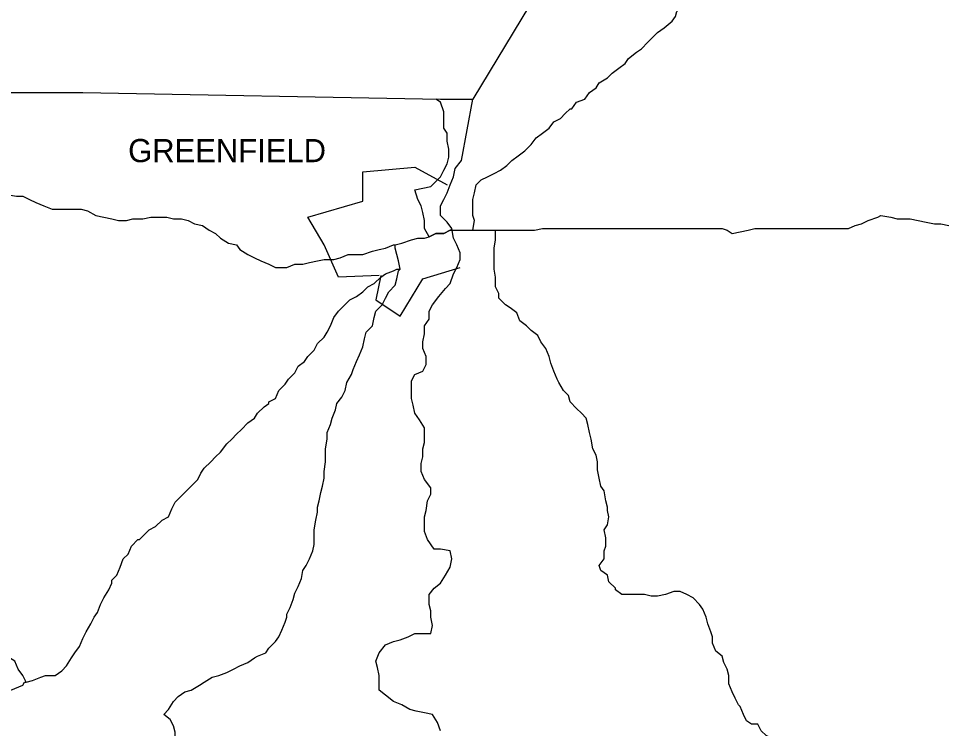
# Model space of a CAD drawing. Extents: x 0 to 40.2, y 0 to 22.
# Drawn here: x 4.34 to 5.119, y 18.795 to 19.393 of the extents above; entities that cross this region are included whole.
import ezdxf

# ---------------------------------------------------------------- set-up
doc = ezdxf.new("R2010")
doc.units = 0
doc.layers.add('Default', color=7, linetype='Continuous')

msp = doc.modelspace()

# ---------------------------------------------------------------- linework, layer by layer
at = {"layer": 'Default'}
for points in [[(5.09948, 19.94935), (5.06676, 19.89345), (4.97541, 19.74211), (4.72318, 19.3249)], [(4.80634, 19.31672), (4.81043, 19.32217), (4.81725, 19.3249), (4.82134, 19.33035), (4.8268, 19.33444), (4.82952, 19.33853), (4.83634, 19.34262), (4.84043, 19.34671), (4.84588, 19.3508), (4.85134, 19.35489), (4.85406, 19.35898), (4.86088, 19.36444), (4.86497, 19.36716), (4.87042, 19.37262), (4.87588, 19.37807), (4.87861, 19.3808), (4.88406, 19.38489), (4.89088, 19.39034), (4.8936, 19.39443), (4.89497, 19.39852), (4.89633, 19.39989)], [(3.95693, 19.3399), (4.11782, 19.33581), (4.31142, 19.33035), (4.39459, 19.33035), (4.69591, 19.3249), (4.72318, 19.3249)], [(4.69591, 18.79316), (4.69318, 18.79998), (4.68909, 18.8068), (4.68227, 18.80816), (4.67546, 18.80953), (4.67, 18.81089), (4.66318, 18.81498), (4.65637, 18.81771), (4.64955, 18.82316), (4.6441, 18.82725), (4.6441, 18.83407), (4.6441, 18.83952), (4.64273, 18.84634), (4.64137, 18.85179), (4.6441, 18.85861), (4.64955, 18.86543), (4.65637, 18.86815), (4.66182, 18.86952), (4.66864, 18.87224), (4.67409, 18.87497), (4.68091, 18.87497), (4.68773, 18.87497), (4.68909, 18.88179), (4.68773, 18.8886), (4.68773, 18.89406), (4.68636, 18.89951), (4.68636, 18.90769), (4.69045, 18.91315), (4.69591, 18.91724), (4.7, 18.92405), (4.70409, 18.93087), (4.70545, 18.93769), (4.70409, 18.9445), (4.69591, 18.94587), (4.69045, 18.94587), (4.685, 18.95405), (4.68227, 18.96087), (4.68227, 18.96632), (4.68227, 18.97314), (4.68364, 18.97859), (4.685, 18.98677), (4.68773, 18.99222), (4.68773, 18.99768), (4.68227, 19.00449), (4.67955, 19.01131), (4.67955, 19.01813), (4.68091, 19.02358), (4.68091, 19.0304), (4.68227, 19.03585), (4.68227, 19.04267), (4.68227, 19.04812), (4.67818, 19.05494), (4.67409, 19.0604), (4.67273, 19.06721), (4.67137, 19.07267), (4.67137, 19.07948), (4.67137, 19.08766), (4.67409, 19.09312), (4.68091, 19.09584), (4.68364, 19.1013), (4.68364, 19.10811), (4.68091, 19.11493), (4.68091, 19.12039), (4.68227, 19.1272), (4.68227, 19.13402), (4.68636, 19.13947), (4.68636, 19.14629), (4.68909, 19.15174), (4.69454, 19.15856), (4.7, 19.16538), (4.70409, 19.16947), (4.70681, 19.17765), (4.70954, 19.1831), (4.71227, 19.18992), (4.71227, 19.19537), (4.70954, 19.20219), (4.70681, 19.20764), (4.70545, 19.21583), (4.70136, 19.22128), (4.69591, 19.22673), (4.69591, 19.23491), (4.69863, 19.24037), (4.70136, 19.24582), (4.70409, 19.25264), (4.70681, 19.25945), (4.70818, 19.26627), (4.71363, 19.27309), (4.72318, 19.3249)], [(4.68636, 19.20901), (4.68227, 19.21583), (4.68227, 19.22264), (4.68091, 19.22946), (4.67955, 19.23491), (4.67682, 19.24037), (4.67409, 19.24855), (4.68091, 19.24991), (4.68773, 19.25127), (4.69182, 19.25536), (4.69591, 19.25945), (4.69863, 19.26491), (4.70136, 19.27036), (4.70272, 19.27582), (4.70272, 19.28263), (4.70136, 19.28945), (4.70136, 19.29627), (4.69863, 19.30036), (4.69863, 19.30854), (4.69863, 19.31399), (4.69591, 19.32217), (4.69182, 19.3249)], [(4.77226, 19.28672), (4.77635, 19.29218), (4.7818, 19.29627), (4.78726, 19.30036), (4.79135, 19.30581), (4.7968, 19.30854), (4.80089, 19.31263), (4.80498, 19.31672), (4.80634, 19.31672)], [(4.72318, 19.21446), (4.72454, 19.22264), (4.72318, 19.22673), (4.72318, 19.23491), (4.72318, 19.24037), (4.72454, 19.24582), (4.7259, 19.25264), (4.72999, 19.25673), (4.73545, 19.25945), (4.7409, 19.26218), (4.74635, 19.26491), (4.75181, 19.269), (4.7559, 19.27309), (4.76135, 19.27718), (4.7668, 19.28127), (4.77226, 19.28672), (4.77226, 19.28672)], [(4.6441, 19.17629), (4.61001, 19.17492), (4.59774, 19.20219), (4.58411, 19.22537), (4.63046, 19.239), (4.63046, 19.26354), (4.67409, 19.26764), (4.70136, 19.25264)], [(4.3196, 19.24446), (4.32506, 19.24446), (4.33051, 19.24446), (4.33869, 19.24309), (4.34414, 19.24309), (4.3496, 19.24037), (4.35505, 19.23764), (4.36187, 19.23491), (4.36869, 19.23219), (4.37414, 19.23219), (4.37959, 19.23219), (4.38641, 19.23219), (4.39323, 19.23219), (4.39868, 19.23082), (4.4055, 19.22673), (4.41232, 19.22537), (4.41913, 19.22401), (4.42459, 19.22264), (4.4314, 19.22264), (4.43686, 19.22401), (4.43822, 19.22401)], [(4.43822, 19.22401), (4.44504, 19.22401), (4.45185, 19.22537), (4.45867, 19.22537), (4.46549, 19.22537), (4.47094, 19.22401), (4.47776, 19.22401), (4.48321, 19.22264), (4.48867, 19.21992), (4.49548, 19.21855), (4.50094, 19.21446), (4.50639, 19.21173), (4.51048, 19.20764), (4.5173, 19.20355), (4.52412, 19.20219), (4.52684, 19.1981), (4.53366, 19.19401), (4.53911, 19.19128), (4.54457, 19.18856), (4.55138, 19.18583), (4.55684, 19.1831), (4.55956, 19.1831), (4.55956, 19.1831)], [(4.74226, 19.21446), (4.74772, 19.21446), (4.7559, 19.21446), (4.76271, 19.21446), (4.76953, 19.21446), (4.77499, 19.21446), (4.7818, 19.21583), (4.78726, 19.21583), (4.79407, 19.21583), (4.80089, 19.21583), (4.80771, 19.21583), (4.81452, 19.21583), (4.82134, 19.21583), (4.8268, 19.21583), (4.83498, 19.21583), (4.84043, 19.21583), (4.84588, 19.21583), (4.8527, 19.21583), (4.85952, 19.21583), (4.86633, 19.21583), (4.87315, 19.21583), (4.87861, 19.21583), (4.88542, 19.21583), (4.89224, 19.21583), (4.89906, 19.21583), (4.90587, 19.21583), (4.91133, 19.21583), (4.91951, 19.21583), (4.92496, 19.21583), (4.93314, 19.21583), (4.93723, 19.21446), (4.94132, 19.21173), (4.94814, 19.2131), (4.95496, 19.21446), (4.96041, 19.21583), (4.96723, 19.21583), (4.97404, 19.21583), (4.98086, 19.21583), (4.98768, 19.21583), (4.99313, 19.21583), (4.99995, 19.21583), (5.00677, 19.21583), (5.01222, 19.21583), (5.0204, 19.21583), (5.02585, 19.21583), (5.03267, 19.21583), (5.03949, 19.21583), (5.04494, 19.21855), (5.0504, 19.21992), (5.05585, 19.22264), (5.06403, 19.22537), (5.06676, 19.22673), (5.07494, 19.22537), (5.08039, 19.22401), (5.08857, 19.22401), (5.0913, 19.22401), (5.0913, 19.22401)], [(5.0913, 19.22401), (5.09812, 19.22264), (5.10493, 19.22128), (5.11175, 19.21992), (5.1172, 19.21992), (5.12402, 19.21855)], [(4.70545, 19.21446), (4.70409, 19.21446), (4.69863, 19.21173), (4.69182, 19.21173), (4.68636, 19.20901)], [(4.68636, 19.20901), (4.69182, 19.21173), (4.69863, 19.21173), (4.70409, 19.21446), (4.70545, 19.21446)], [(4.68636, 19.20901), (4.69182, 19.21173), (4.69863, 19.21173), (4.70409, 19.21446), (4.70545, 19.21446)], [(4.70545, 19.21446), (4.71227, 19.21446), (4.71772, 19.21446), (4.72318, 19.21446), (4.72318, 19.21446)], [(4.72318, 19.21446), (4.72999, 19.21446), (4.73681, 19.21446), (4.74226, 19.21446), (4.74226, 19.21446)], [(4.79407, 19.08903), (4.79135, 19.09584), (4.78862, 19.10266), (4.78726, 19.10811), (4.78453, 19.11493), (4.78044, 19.12039), (4.77771, 19.12584), (4.77226, 19.12993), (4.76817, 19.13402), (4.76271, 19.13811), (4.75999, 19.14493), (4.75453, 19.14902), (4.75044, 19.15174), (4.74499, 19.1572), (4.74499, 19.16129), (4.74226, 19.16674), (4.74226, 19.17492), (4.7409, 19.18174), (4.7409, 19.18719), (4.7409, 19.19401), (4.7409, 19.19946), (4.74226, 19.20628), (4.74226, 19.21173), (4.74226, 19.21446)], [(4.65773, 19.20219), (4.66318, 19.20355), (4.67137, 19.20628), (4.67682, 19.20764), (4.68227, 19.20764), (4.68636, 19.20901)], [(4.65773, 19.20219), (4.66318, 19.20355), (4.67137, 19.20628), (4.67682, 19.20764), (4.68227, 19.20764), (4.68636, 19.20901)], [(4.55956, 19.1831), (4.56638, 19.1831), (4.5732, 19.18583), (4.58002, 19.18583), (4.58547, 19.18719), (4.59229, 19.18856), (4.59774, 19.18992), (4.60592, 19.18992), (4.61137, 19.19128), (4.61819, 19.19401), (4.62501, 19.19401), (4.63046, 19.19401), (4.63864, 19.19674), (4.6441, 19.1981), (4.64955, 19.19946), (4.65637, 19.20219), (4.65773, 19.20219)], [(4.66182, 19.18174), (4.66046, 19.18856), (4.65909, 19.19401), (4.65773, 19.19946), (4.65773, 19.20219)], [(4.55138, 19.06994), (4.55684, 19.07267), (4.55956, 19.07948), (4.56502, 19.08494), (4.56775, 19.08903), (4.5732, 19.09448), (4.57593, 19.09993), (4.58138, 19.10402), (4.58411, 19.10811), (4.58956, 19.11357), (4.59229, 19.11902), (4.59774, 19.12448), (4.60047, 19.12857), (4.60319, 19.13402), (4.60592, 19.14084), (4.61001, 19.14629), (4.6141, 19.15038), (4.61956, 19.15583), (4.62501, 19.15856), (4.63046, 19.16265), (4.63455, 19.16674), (4.64001, 19.16947), (4.64546, 19.17492), (4.64955, 19.17765), (4.65637, 19.18038), (4.65909, 19.18174), (4.66182, 19.18174)], [(4.59229, 18.98132), (4.59365, 18.98677), (4.59501, 18.99359), (4.59638, 18.99904), (4.59774, 19.00586), (4.59774, 19.01131), (4.5991, 19.01949), (4.5991, 19.02358), (4.5991, 19.0304), (4.60047, 19.03858), (4.60047, 19.04403), (4.60319, 19.05085), (4.60456, 19.0563), (4.60728, 19.06312), (4.60865, 19.06858), (4.61274, 19.07403), (4.61547, 19.07948), (4.61683, 19.0863), (4.62092, 19.09312), (4.62228, 19.09721), (4.62501, 19.10402), (4.62774, 19.10948), (4.63046, 19.1163), (4.63183, 19.12311), (4.63319, 19.12857), (4.63864, 19.13402), (4.64001, 19.14084), (4.64137, 19.14629), (4.64682, 19.15174), (4.64955, 19.1572), (4.65228, 19.16265), (4.65773, 19.16811), (4.65909, 19.17356), (4.66046, 19.18038), (4.66182, 19.18174)], [(4.64546, 19.17629), (4.64137, 19.15583), (4.66182, 19.1422), (4.68091, 19.17356), (4.71227, 19.1831)], [(4.83634, 18.98132), (4.83498, 18.98677), (4.83361, 18.99495), (4.83089, 18.99904), (4.82952, 19.00586), (4.82816, 19.01268), (4.82816, 19.01949), (4.8268, 19.02495), (4.82407, 19.0304), (4.82271, 19.03858), (4.82134, 19.04403), (4.81998, 19.05085), (4.81861, 19.0563), (4.81452, 19.0604), (4.81043, 19.06449), (4.80498, 19.06994), (4.80362, 19.07539), (4.79953, 19.07948), (4.79544, 19.0863), (4.79407, 19.08903)], [(4.44231, 18.95405), (4.44504, 18.95678), (4.45049, 18.96223), (4.45595, 18.96496), (4.4614, 18.97041), (4.46685, 18.97314), (4.46958, 18.97995), (4.47231, 18.98541), (4.47776, 18.99086), (4.48185, 18.99495), (4.48594, 18.99904), (4.49139, 19.00449), (4.49412, 19.00995), (4.49685, 19.01404), (4.5023, 19.01949), (4.50639, 19.02358), (4.51048, 19.02767), (4.51594, 19.03449), (4.52003, 19.03858), (4.52412, 19.04267), (4.52821, 19.04676), (4.53366, 19.05221), (4.53911, 19.0563), (4.54184, 19.0604), (4.54729, 19.06585), (4.55138, 19.06858), (4.55138, 19.06994)], [(4.56638, 18.89133), (4.56911, 18.89678), (4.57184, 18.9036), (4.5732, 18.90906), (4.57593, 18.91451), (4.57865, 18.92133), (4.58002, 18.92814), (4.58274, 18.93223), (4.58547, 18.93769), (4.5882, 18.9445), (4.58956, 18.94996), (4.58956, 18.95678), (4.58956, 18.96223), (4.59092, 18.97041), (4.59229, 18.97723), (4.59229, 18.98132)], [(4.84316, 18.91315), (4.8377, 18.9186), (4.83634, 18.92405), (4.83089, 18.92814), (4.82952, 18.93223), (4.83361, 18.93769), (4.83361, 18.9445), (4.83498, 18.94859), (4.83498, 18.95541), (4.83361, 18.96223), (4.83634, 18.96632), (4.8377, 18.97314), (4.83634, 18.97859), (4.83634, 18.97995), (4.83634, 18.98132)], [(4.41913, 18.91996), (4.42322, 18.92405), (4.42595, 18.93087), (4.42868, 18.93769), (4.43277, 18.94178), (4.43549, 18.94859), (4.44095, 18.95405), (4.44231, 18.95405)], [(4.34687, 18.83407), (4.34414, 18.83952), (4.34005, 18.84497), (4.33733, 18.85179), (4.33051, 18.85588), (4.32915, 18.85861), (4.32778, 18.86406), (4.32097, 18.86679), (4.31551, 18.86952), (4.31142, 18.87497), (4.30597, 18.8777), (4.30052, 18.88042), (4.29506, 18.88315), (4.28961, 18.88724), (4.28552, 18.89269), (4.28143, 18.89678), (4.27734, 18.90224), (4.27188, 18.90769), (4.27052, 18.91178), (4.26507, 18.91724), (4.2637, 18.91724), (4.2637, 18.91724)], [(4.34687, 18.83407), (4.35233, 18.83543), (4.35914, 18.83816), (4.36323, 18.83952), (4.37141, 18.83952), (4.37687, 18.84361), (4.38096, 18.8477), (4.38505, 18.85452), (4.38777, 18.85861), (4.39186, 18.86406), (4.39459, 18.87088), (4.39732, 18.87633), (4.40141, 18.88315), (4.40414, 18.8886), (4.40686, 18.89269), (4.40959, 18.89951), (4.41232, 18.90497), (4.41641, 18.91178), (4.41913, 18.91724), (4.41913, 18.91996)], [(4.94678, 18.81498), (4.94405, 18.82043), (4.94132, 18.82589), (4.9386, 18.8327), (4.9386, 18.83952), (4.93723, 18.84497), (4.93451, 18.85043), (4.93314, 18.85588), (4.92769, 18.85997), (4.92496, 18.86679), (4.92496, 18.87224), (4.9236, 18.87633), (4.92087, 18.88315), (4.91951, 18.8886), (4.91678, 18.89542), (4.91405, 18.89951), (4.9086, 18.90497), (4.90315, 18.90769), (4.89769, 18.91042), (4.89224, 18.91042), (4.88542, 18.90769), (4.87861, 18.90633), (4.87315, 18.90633), (4.8677, 18.90769), (4.86088, 18.90769), (4.85406, 18.90769), (4.84861, 18.90769), (4.84316, 18.91178), (4.84316, 18.91315), (4.84316, 18.91315)], [(4.54184, 18.85588), (4.54866, 18.85861), (4.55138, 18.8627), (4.55684, 18.86815), (4.55956, 18.87224), (4.56229, 18.8777), (4.56502, 18.88451), (4.56638, 18.8886), (4.56638, 18.89133)], [(4.46276, 18.8068), (4.46685, 18.81089), (4.47094, 18.81771), (4.47503, 18.8218), (4.48049, 18.82589), (4.48594, 18.82725), (4.49276, 18.83134), (4.49685, 18.83407), (4.50366, 18.83816), (4.50912, 18.83952), (4.51594, 18.84225), (4.52139, 18.84497), (4.52684, 18.8477), (4.53366, 18.85043), (4.53911, 18.85452), (4.54184, 18.85588)], [(4.26098, 18.83134), (4.26643, 18.83407), (4.27188, 18.83407), (4.2787, 18.83134), (4.28552, 18.82998), (4.28961, 18.82589), (4.29506, 18.8218), (4.30052, 18.82043), (4.30597, 18.82316), (4.31279, 18.82316), (4.3196, 18.82452), (4.32642, 18.82452), (4.33051, 18.82589), (4.33733, 18.82861), (4.34414, 18.83134), (4.34551, 18.83407), (4.34687, 18.83407)], [(5.02585, 18.74817), (5.02176, 18.74817), (5.01495, 18.7509), (5.00949, 18.75226), (5.00677, 18.75772), (5.00268, 18.76317), (4.99859, 18.7659), (4.99313, 18.77135), (4.99177, 18.7768), (4.98632, 18.78089), (4.98223, 18.78362), (4.97541, 18.78635), (4.96995, 18.78907), (4.96586, 18.79316), (4.96314, 18.79862), (4.95768, 18.79862), (4.95359, 18.80135), (4.95087, 18.8068), (4.94814, 18.81362), (4.94678, 18.81498), (4.94678, 18.81498)], [(4.48458, 18.72772), (4.48321, 18.73454), (4.48185, 18.74135), (4.48049, 18.74681), (4.47776, 18.75226), (4.47776, 18.75908), (4.4764, 18.7659), (4.47503, 18.77271), (4.47503, 18.77817), (4.47231, 18.78498), (4.47231, 18.7918), (4.47094, 18.79725), (4.46822, 18.80271), (4.46276, 18.8068)]]:
    msp.add_lwpolyline(points, dxfattribs=at)

# ---------------------------------------------------------------- texts
msp.add_text('GREENFIELD', height=0.019502, dxfattribs=at).set_placement((4.43277, 19.27173))

doc.saveas('drawing.dxf')
